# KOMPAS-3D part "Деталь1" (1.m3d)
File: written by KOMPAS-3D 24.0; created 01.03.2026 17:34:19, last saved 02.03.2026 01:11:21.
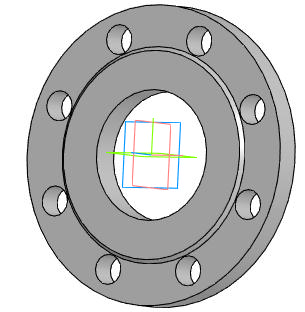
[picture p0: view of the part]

Document properties: Автор: R2D2; Полное имя файла: E:\Работа\Зайцев\GVWR3131M-2W-F-S Задвижка клиновая 30нж64нж DN.ru  Ду50-150 Ру25\исходные данные\DN100\1.m3d

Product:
- Part/product: Деталь1
    Масса: 5.317036
    additional columns: Типовые

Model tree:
1. Эскиз:2
2. Элемент вращения:1
     Угол 1 = 360
3. Эскиз:3  (with: Грань.Элемент вращения:1)
4. Элемент выдавливания:2
     Расстояние 2 = 21
5. Массив по концентрической сетке:1  (with: Элемент выдавливания:2, Эскиз:3, Грань.Элемент вращения:1)  (8 pattern instances)
     Шаг 2 = 360
6. Эскиз:4  (with: Грань.Элемент вращения:1)
7. Элемент выдавливания:3
     Расстояние 2 = 3

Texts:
  Линейный размер с обрывом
